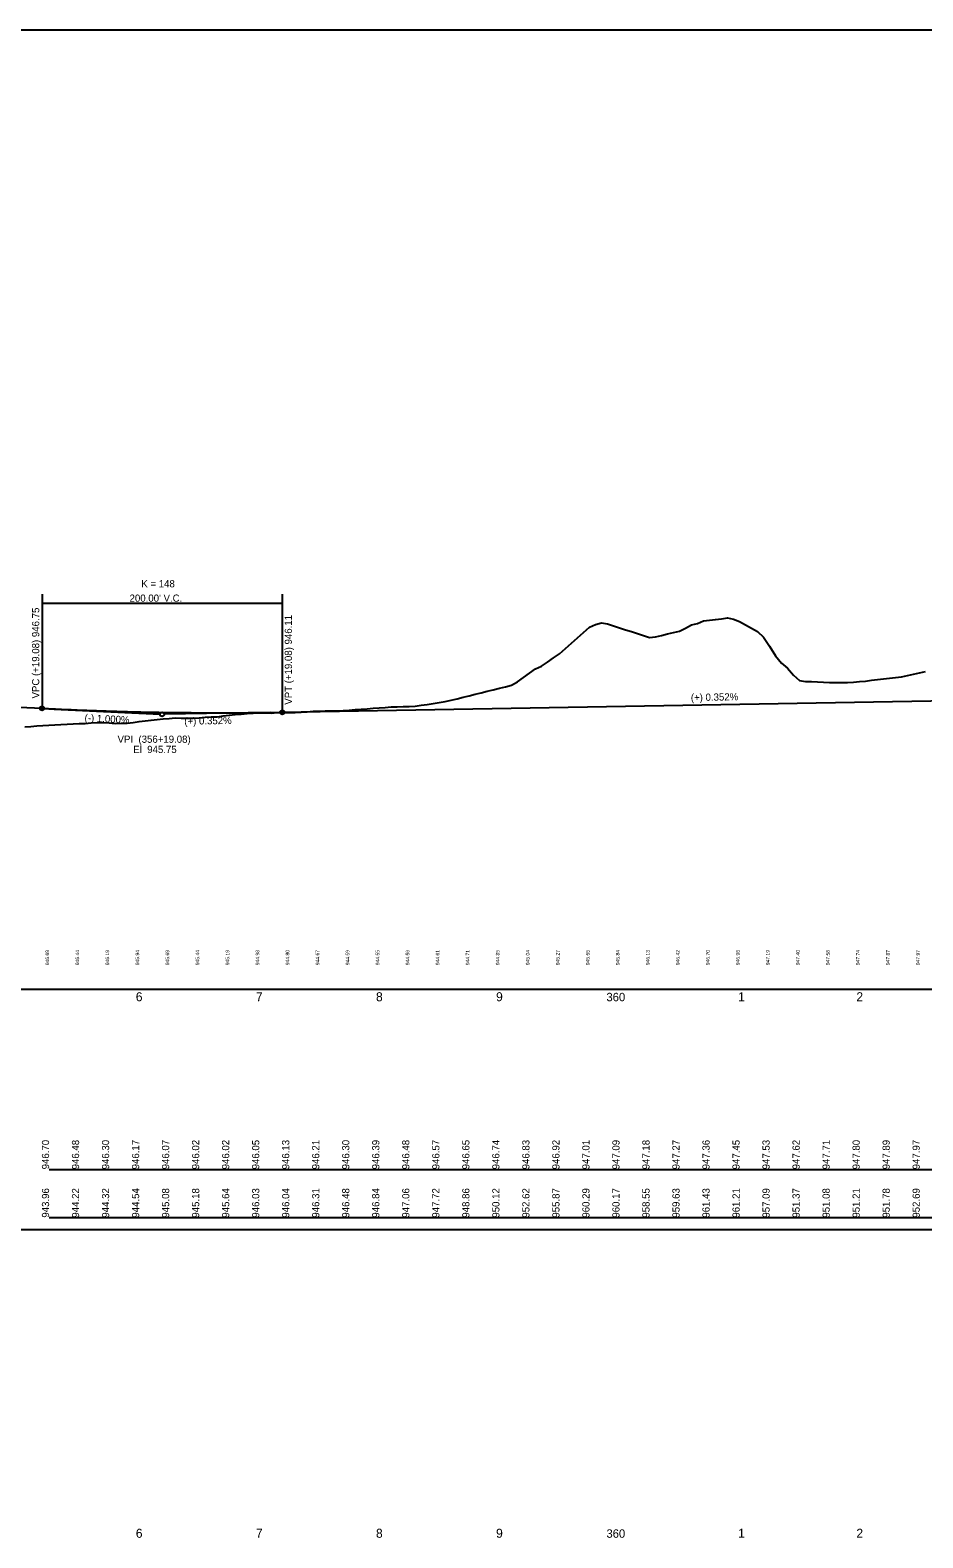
# Model space of a CAD drawing. Extents: x 2150 to 16979375, y 5011 to 12565288.
# Drawn here: x 16975728 to 16976471, y 12563831 to 12565086 of the extents above; entities that cross this region are included whole.
import ezdxf

# ---------------------------------------------------------------- set-up
doc = ezdxf.new("R2010")
doc.units = 0
for name, color, linetype in [('BR_REBAR', 7, 'Continuous'), ('BR_SHEET_NUM', 7, 'Continuous'), ('BR_SITE LOCATION', 7, 'Continuous'), ('Default', 7, 'Continuous'), ('RD_DDB_GradeTX', 7, 'Continuous'), ('RD_DDB_StripGrade_EX', 7, 'Continuous'), ('RD_DTM_Obscure', 7, 'Continuous'), ('RD_HC_Data', 7, 'Continuous'), ('RD_HC_Data_Tic', 7, 'Continuous'), ('RD_HC_Points', 7, 'Continuous'), ('RD_HC_TX_Sta20', 7, 'Continuous')]:
    doc.layers.add(name, color=color, linetype=linetype)

msp = doc.modelspace()

# ---------------------------------------------------------------- linework, layer by layer
at = {"layer": 'BR_REBAR'}
for p, q in [((16975737.6, 12564616.6), (16975737.6, 12564523.3)), ((16975937.6, 12564616.6), (16975937.6, 12564520.1)), ((16975737.6, 12564609.1), (16975937.6, 12564609.1))]:
    msp.add_line(p, q, dxfattribs=at)
for centre in [(16975737.6, 12564521.6), (16975937.6, 12564518.3)]:
    msp.add_circle(centre, 1.75, dxfattribs=at)
at = {"layer": 'BR_SHEET_NUM'}
for p, q in [((16975747.7, 12564521), (16975835.9, 12564516.6)), ((16975927.6, 12564518.1), (16975839.4, 12564516.6))]:
    msp.add_line(p, q, dxfattribs=at)
msp.add_circle((16975837.6, 12564516.6), 1.75, dxfattribs=at)
at = {"layer": 'BR_SITE LOCATION'}
for p, q in [((16975937.6, 12564518.3), (16976493.5, 12564528.1)), ((16975718.5, 12564522.5), (16975737.6, 12564521.6))]:
    msp.add_line(p, q, dxfattribs=at)
msp.add_spline([(16975737.6, 12564521.6), (16975741.6, 12564521.4), (16975745.6, 12564521.2), (16975749.6, 12564521), (16975753.6, 12564520.8), (16975757.6, 12564520.6), (16975761.6, 12564520.5), (16975765.6, 12564520.3), (16975769.6, 12564520.1), (16975773.6, 12564520), (16975777.6, 12564519.8), (16975781.6, 12564519.7), (16975785.6, 12564519.5), (16975789.6, 12564519.4), (16975793.6, 12564519.3), (16975797.6, 12564519.2), (16975801.6, 12564519), (16975805.6, 12564518.9), (16975809.6, 12564518.8), (16975813.6, 12564518.7), (16975817.6, 12564518.6), (16975821.6, 12564518.5), (16975825.6, 12564518.5), (16975829.6, 12564518.4), (16975833.6, 12564518.3), (16975837.6, 12564518.2), (16975841.6, 12564518.2), (16975845.6, 12564518.1), (16975849.6, 12564518.1), (16975853.6, 12564518), (16975857.6, 12564518), (16975861.6, 12564518), (16975865.6, 12564517.9), (16975869.6, 12564517.9), (16975873.6, 12564517.9), (16975877.6, 12564517.9), (16975881.6, 12564517.9), (16975885.6, 12564517.9), (16975889.6, 12564517.9), (16975893.6, 12564517.9), (16975897.6, 12564517.9), (16975901.6, 12564517.9), (16975905.6, 12564517.9), (16975909.6, 12564518), (16975913.6, 12564518), (16975917.6, 12564518), (16975921.6, 12564518.1), (16975925.6, 12564518.1), (16975929.6, 12564518.2), (16975933.6, 12564518.2), (16975937.6, 12564518.3)], degree=3, dxfattribs=at)
at = {"layer": 'Default'}
msp.add_lwpolyline([(16975718.5, 12564087.8), (16977218.5, 12564087.8), (16977218.5, 12565086), (16975718.5, 12565086)], close=True, dxfattribs=at)
at = {"layer": 'RD_DTM_Obscure'}
for p, q in [((16975743.5, 12564137.8), (16977217.6, 12564137.8)), ((16975743.5, 12564097.7), (16977217.6, 12564097.7))]:
    msp.add_line(p, q, dxfattribs=at)
at = {"layer": 'RD_HC_Data'}
msp.add_line((16972985.6, 12564287.8), (16979375.1, 12564287.8), dxfattribs=at)
at = {"layer": 'RD_HC_Points'}
for points in [[(16975998.4, 12564520.6), (16976003.4, 12564521), (16976008.4, 12564521.3), (16976013.4, 12564521.7), (16976018.4, 12564522), (16976023.4, 12564522.3), (16976028.4, 12564522.7), (16976033.4, 12564522.9), (16976038.4, 12564523), (16976043.4, 12564523.1), (16976048.4, 12564523.4), (16976053.4, 12564524.1), (16976058.4, 12564524.8), (16976063.4, 12564525.5), (16976068.4, 12564526.4), (16976073.4, 12564527.4), (16976078.4, 12564528.5), (16976083.4, 12564529.6), (16976088.4, 12564530.9), (16976093.4, 12564532.1), (16976098.4, 12564533.3), (16976103.4, 12564534.5), (16976108.4, 12564535.8), (16976113.4, 12564537.1), (16976118.4, 12564538.3), (16976123.4, 12564539.6), (16976128.4, 12564541), (16976133.4, 12564543.6), (16976138.4, 12564547.2), (16976143.4, 12564550.8), (16976148.4, 12564554.4), (16976153.4, 12564556.7), (16976158.4, 12564559.9), (16976163.4, 12564563.5), (16976168.4, 12564567), (16976173.4, 12564571.4), (16976178.4, 12564575.8), (16976183.4, 12564580.3), (16976188.4, 12564584.8), (16976193.4, 12564589.2), (16976198.4, 12564591.3), (16976203.4, 12564592.8), (16976208.4, 12564591.9), (16976213.4, 12564590.3), (16976218.4, 12564588.6), (16976223.4, 12564587), (16976228.4, 12564585.4), (16976233.4, 12564583.8), (16976238.4, 12564582.2), (16976243.4, 12564580.5), (16976248.4, 12564581.1), (16976253.4, 12564582.3), (16976258.4, 12564583.5), (16976263.4, 12564584.7), (16976268.4, 12564585.9), (16976273.4, 12564588.3), (16976278.4, 12564591), (16976283.4, 12564592.2), (16976288.4, 12564594.3), (16976293.4, 12564594.9), (16976298.4, 12564595.6), (16976303.4, 12564596.2), (16976308.4, 12564596.9), (16976313.4, 12564595.7), (16976318.4, 12564593.9), (16976323.4, 12564591.1), (16976328.4, 12564588.2), (16976333.4, 12564585.5), (16976338.4, 12564580.9), (16976343.4, 12564573.4), (16976348.4, 12564565.3), (16976353.4, 12564559.1), (16976358.4, 12564555), (16976363.4, 12564549.1), (16976368.4, 12564544.7), (16976373.4, 12564543.8), (16976378.4, 12564543.8), (16976383.4, 12564543.7), (16976388.4, 12564543.4), (16976393.4, 12564543.2), (16976398.4, 12564543), (16976403.4, 12564543), (16976408.4, 12564543.1), (16976413.4, 12564543.3), (16976418.4, 12564543.8), (16976423.4, 12564544.3), (16976428.4, 12564544.9), (16976433.4, 12564545.5), (16976438.4, 12564546.1), (16976443.4, 12564546.7), (16976448.4, 12564547.2), (16976453.4, 12564547.9), (16976458.4, 12564548.9), (16976463.4, 12564550.1), (16976468.4, 12564551.2), (16976473.4, 12564552.2)], [(16975723.4, 12564506.1), (16975728.4, 12564506.5), (16975733.4, 12564507), (16975738.4, 12564507.3), (16975743.4, 12564507.6), (16975748.4, 12564507.9), (16975753.4, 12564508.2), (16975758.4, 12564508.4), (16975763.4, 12564508.6), (16975768.4, 12564508.9), (16975773.4, 12564509.1), (16975778.4, 12564509.4), (16975783.4, 12564509.7), (16975788.4, 12564509.7), (16975793.4, 12564509.4), (16975798.4, 12564509.1), (16975803.4, 12564509.3), (16975808.4, 12564509.2), (16975813.4, 12564509.8), (16975818.4, 12564510.5), (16975823.4, 12564511.1), (16975828.4, 12564511.8), (16975833.4, 12564512.3), (16975838.4, 12564512.9), (16975843.4, 12564513.2), (16975848.4, 12564513.6), (16975853.4, 12564513.5), (16975858.4, 12564513.5), (16975863.4, 12564513.4), (16975868.4, 12564513.7), (16975873.4, 12564514.1), (16975878.4, 12564514.5), (16975883.4, 12564514.6), (16975888.4, 12564515.4), (16975893.4, 12564516), (16975898.4, 12564516.5), (16975903.4, 12564516.8), (16975908.4, 12564517.3), (16975913.4, 12564517.7), (16975918.4, 12564517.9), (16975923.4, 12564517.8), (16975928.4, 12564517.7), (16975933.4, 12564518), (16975938.4, 12564518), (16975943.4, 12564518), (16975948.4, 12564518.1), (16975953.4, 12564518.4), (16975958.4, 12564518.8), (16975963.4, 12564519.1), (16975968.4, 12564519.3), (16975973.4, 12564519.4), (16975978.4, 12564519.4), (16975983.4, 12564519.5), (16975988.4, 12564519.8), (16975993.4, 12564520.2), (16975998.4, 12564520.6)]]:
    msp.add_lwpolyline(points, dxfattribs=at)

# ---------------------------------------------------------------- texts
at = {"layer": 'BR_REBAR'}
for s, p in [('K = 148', (16975820.3, 12564622.3)), ("200.00' V.C.", (16975810.5, 12564610.3))]:
    msp.add_text(s, height=6, dxfattribs=at).set_placement(p)
for s, p in [('VPC (+19.08) 946.75', (16975735.3, 12564529.8)), ('VPT (+19.08) 946.11', (16975945.7, 12564524.6))]:
    msp.add_text(s, height=6, rotation=90, dxfattribs=at).set_placement(p)
at = {"layer": 'BR_SHEET_NUM'}
for s, p in [('VPI  (356+19.08)', (16975800.5, 12564492.9)), ('El  945.75', (16975813.6, 12564484.4))]:
    msp.add_text(s, height=6, dxfattribs=at).set_placement(p)
at = {"layer": 'RD_DDB_GradeTX'}
for s, rotation, p in [('(+) 0.352%', 1.0082, (16976277.9, 12564527.6)), ('(-) 1.000%', 357.1376, (16975772.9, 12564510.8)), ('(+) 0.352%', 1.0082, (16975856.1, 12564507.9))]:
    msp.add_text(s, height=6, rotation=rotation, dxfattribs=at).set_placement(p)
at = {"layer": 'RD_DDB_StripGrade_EX'}
for s, p in [('943.96', (16975743.5, 12564097.7)), ('944.22', (16975768.5, 12564097.7)), ('944.32', (16975793.5, 12564097.7)), ('944.54', (16975818.5, 12564097.7)), ('945.08', (16975843.5, 12564097.7)), ('945.18', (16975868.5, 12564097.7)), ('945.64', (16975893.5, 12564097.7)), ('946.03', (16975918.5, 12564097.7)), ('946.04', (16975943.5, 12564097.7)), ('946.31', (16975968.5, 12564097.7)), ('946.48', (16975993.5, 12564097.7)), ('946.84', (16976018.5, 12564097.7)), ('947.06', (16976043.5, 12564097.7)), ('947.72', (16976068.5, 12564097.7)), ('948.86', (16976093.5, 12564097.7)), ('950.12', (16976118.5, 12564097.7)), ('952.62', (16976143.5, 12564097.7)), ('955.87', (16976168.5, 12564097.7)), ('960.29', (16976193.5, 12564097.7)), ('960.17', (16976218.5, 12564097.7)), ('958.55', (16976243.5, 12564097.7)), ('959.63', (16976268.5, 12564097.7)), ('961.43', (16976293.5, 12564097.7)), ('961.21', (16976318.5, 12564097.7)), ('957.09', (16976343.5, 12564097.7)), ('951.37', (16976368.5, 12564097.7)), ('951.08', (16976393.5, 12564097.7)), ('951.21', (16976418.5, 12564097.7)), ('951.78', (16976443.5, 12564097.7)), ('952.69', (16976468.5, 12564097.7))]:
    msp.add_text(s, height=6, rotation=90, dxfattribs=at).set_placement(p)
at = {"layer": 'RD_HC_Data_Tic'}
for s, height, p in [('6', 7.5, (16975815.7, 12564277.8)), ('7', 7.5, (16975915.7, 12564277.8)), ('8', 7.5, (16976015.7, 12564277.8)), ('9', 7.5, (16976115.7, 12564277.8)), ('360', 7, (16976207.6, 12564277.8)), ('1', 7.5, (16976317.2, 12564277.8)), ('2', 7.5, (16976415.7, 12564277.8)), ('6', 7.5, (16975815.7, 12563831.3)), ('7', 7.5, (16975915.7, 12563831.3)), ('8', 7.5, (16976015.7, 12563831.3)), ('9', 7.5, (16976115.7, 12563831.3)), ('360', 7, (16976207.6, 12563831.3)), ('1', 7.5, (16976317.2, 12563831.3)), ('2', 7.5, (16976415.7, 12563831.3))]:
    msp.add_text(s, height=height, dxfattribs=at).set_placement(p)
at = {"layer": 'RD_HC_TX_Sta20'}
for s, height, p in [('946.69', 3, (16975743.5, 12564307.8)), ('946.44', 3, (16975768.5, 12564307.8)), ('946.19', 3, (16975793.5, 12564307.8)), ('945.94', 3, (16975818.5, 12564307.8)), ('945.69', 3, (16975843.5, 12564307.8)), ('945.44', 3, (16975868.5, 12564307.8)), ('945.19', 3, (16975893.5, 12564307.8)), ('944.98', 3, (16975918.5, 12564307.8)), ('944.80', 3, (16975943.5, 12564307.8)), ('944.67', 3, (16975968.5, 12564307.8)), ('944.59', 3, (16975993.5, 12564307.8)), ('944.55', 3, (16976018.5, 12564307.8)), ('944.56', 3, (16976043.5, 12564307.8)), ('944.61', 3, (16976068.5, 12564307.8)), ('944.71', 3, (16976093.5, 12564307.8)), ('944.85', 3, (16976118.5, 12564307.8)), ('945.04', 3, (16976143.5, 12564307.8)), ('945.27', 3, (16976168.5, 12564307.8)), ('945.55', 3, (16976193.5, 12564307.8)), ('945.84', 3, (16976218.5, 12564307.8)), ('946.13', 3, (16976243.5, 12564307.8)), ('946.42', 3, (16976268.5, 12564307.8)), ('946.70', 3, (16976293.5, 12564307.8)), ('946.96', 3, (16976318.5, 12564307.8)), ('947.19', 3, (16976343.5, 12564307.8)), ('947.40', 3, (16976368.5, 12564307.8)), ('947.58', 3, (16976393.5, 12564307.8)), ('947.74', 3, (16976418.5, 12564307.8)), ('947.87', 3, (16976443.5, 12564307.8)), ('947.97', 3, (16976468.5, 12564307.8)), ('946.70', 6, (16975743.5, 12564137.9)), ('946.48', 6, (16975768.5, 12564137.9)), ('946.30', 6, (16975793.5, 12564137.9)), ('946.17', 6, (16975818.5, 12564137.9)), ('946.07', 6, (16975843.5, 12564137.9)), ('946.02', 6, (16975868.5, 12564137.9)), ('946.02', 6, (16975893.5, 12564137.9)), ('946.05', 6, (16975918.5, 12564137.9)), ('946.13', 6, (16975943.5, 12564137.9)), ('946.21', 6, (16975968.5, 12564137.9)), ('946.30', 6, (16975993.5, 12564137.9)), ('946.39', 6, (16976018.5, 12564137.9)), ('946.48', 6, (16976043.5, 12564137.9)), ('946.57', 6, (16976068.5, 12564137.9)), ('946.65', 6, (16976093.5, 12564137.9)), ('946.74', 6, (16976118.5, 12564137.9)), ('946.83', 6, (16976143.5, 12564137.9)), ('946.92', 6, (16976168.5, 12564137.9)), ('947.01', 6, (16976193.5, 12564137.9)), ('947.09', 6, (16976218.5, 12564137.9)), ('947.18', 6, (16976243.5, 12564137.9)), ('947.27', 6, (16976268.5, 12564137.9)), ('947.36', 6, (16976293.5, 12564137.9)), ('947.45', 6, (16976318.5, 12564137.9)), ('947.53', 6, (16976343.5, 12564137.9)), ('947.62', 6, (16976368.5, 12564137.9)), ('947.71', 6, (16976393.5, 12564137.9)), ('947.80', 6, (16976418.5, 12564137.9)), ('947.89', 6, (16976443.5, 12564137.9)), ('947.97', 6, (16976468.5, 12564137.9))]:
    msp.add_text(s, height=height, rotation=90, dxfattribs=at).set_placement(p)

doc.saveas('drawing.dxf')
